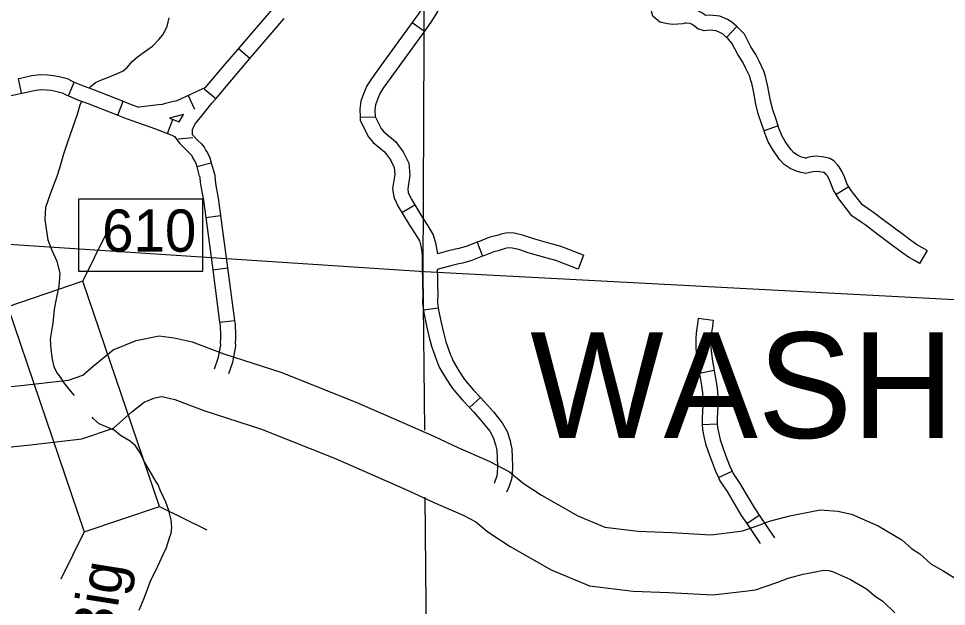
# Model space of a CAD drawing. Extents: x -492261 to -432772, y 1441225 to 1452922.
# Drawn here: x -463909.6 to -463644.7, y 1451410.6 to 1451578.4 of the extents above; entities that cross this region are included whole.
import ezdxf

# ---------------------------------------------------------------- set-up
doc = ezdxf.new("R2010")
doc.units = 0
doc.layers.add('Default', color=7, linetype='Continuous')

msp = doc.modelspace()

# ---------------------------------------------------------------- linework, layer by layer
at = {"layer": 'Default'}
for p, q in [((-463797.21, 1451577.35), (-463793.73, 1451574.84)), ((-463704.55, 1451576.19), (-463707.46, 1451573.04)), ((-463843.55, 1451567.04), (-463846.8, 1451569.83)), ((-463908.78, 1451557.09), (-463909.59, 1451561.3)), ((-463895.36, 1451556.36), (-463893.73, 1451560.32)), ((-463853.3, 1451555.56), (-463856.58, 1451558.32)), ((-463881.28, 1451550.86), (-463879.71, 1451554.85)), ((-463861.14, 1451556.48), (-463859.35, 1451552.58)), ((-463867.1, 1451545.64), (-463865.57, 1451549.65)), ((-463812.07, 1451550.25), (-463807.79, 1451550.39)), ((-463692.69, 1451547.78), (-463696.75, 1451546.41)), ((-463859.79, 1451544.41), (-463864.06, 1451544.04)), ((-463858.73, 1451536.18), (-463854.57, 1451537.23)), ((-463672.49, 1451530.41), (-463676.17, 1451528.21)), ((-463800.13, 1451523.01), (-463796.47, 1451525.24)), ((-463856.14, 1451521.61), (-463851.89, 1451522.17)), ((-463891.21, 1451503.41), (-463884.54, 1451516.94)), ((-463778.61, 1451514.56), (-463777.11, 1451510.54)), ((-463650.2, 1451512.21), (-463652.31, 1451508.49)), ((-463748.3, 1451510.9), (-463749.85, 1451506.9)), ((-463854.16, 1451506.65), (-463849.91, 1451507.22)), ((-463794, 1451495.26), (-463789.75, 1451495.81)), ((-463852.18, 1451491.7), (-463847.93, 1451492.26)), ((-463715.51, 1451492.87), (-463711.26, 1451492.31)), ((-463715.19, 1451477.22), (-463710.98, 1451478.03)), ((-463780.87, 1451467.33), (-463777.71, 1451470.23)), ((-463714.36, 1451462.51), (-463710.08, 1451462.74)), ((-463709.77, 1451447.39), (-463705.87, 1451449.17)), ((-463869.38, 1451439.13), (-463855.85, 1451432.46)), ((-463701.68, 1451434.26), (-463698.13, 1451436.66)), ((-463890.81, 1451431.86), (-463897.48, 1451418.32))]:
    msp.add_line(p, q, dxfattribs=at)
for points in [[(-463790.72, 1451742.44), (-463793.52, 1451659.39), (-463794.14, 1451505.86), (-463793.73, 1451460.92)], [(-463789.44, 1451589.89), (-463790.22, 1451588.38), (-463792.32, 1451584.92), (-463794.15, 1451581.78), (-463795.44, 1451579.79), (-463797.21, 1451577.35)], [(-463785.63, 1451587.93), (-463786.48, 1451586.29), (-463788.64, 1451582.73), (-463790.5, 1451579.53), (-463791.91, 1451577.37), (-463793.73, 1451574.84)], [(-463719.23, 1451577.08), (-463719.95, 1451576.89), (-463722.77, 1451576.76), (-463724.27, 1451576.97), (-463726.5, 1451577.41), (-463728.51, 1451579.11), (-463728.88, 1451580.55), (-463728.96, 1451582.01), (-463728.99, 1451585.28), (-463729.26, 1451586.93), (-463729.4, 1451587.74)], [(-463846.8, 1451569.83), (-463836.99, 1451581.24), (-463836.93, 1451581.31)], [(-463704.55, 1451576.19), (-463705.9, 1451577.44), (-463707.22, 1451578.18), (-463709.32, 1451579.11), (-463712.3, 1451579.38), (-463713.35, 1451579.29), (-463713.56, 1451579.36), (-463714.27, 1451579.94), (-463715.22, 1451580.46), (-463716.55, 1451581.18), (-463719.28, 1451581.5), (-463720.3, 1451581.23)], [(-463889.24, 1451558.7), (-463889.12, 1451558.9), (-463887.65, 1451560.18), (-463885.89, 1451560.94), (-463883.61, 1451561.83), (-463882.53, 1451562.24), (-463881.34, 1451562.71), (-463879.75, 1451563.47), (-463878.45, 1451564.57), (-463877.16, 1451566.19), (-463875.63, 1451567.52), (-463873.25, 1451569.21), (-463871.33, 1451570.6), (-463869.52, 1451572.46), (-463868.4, 1451573.78), (-463867.17, 1451576.14), (-463866.56, 1451578.61)], [(-463843.55, 1451567.04), (-463833.77, 1451578.41), (-463833.74, 1451578.44)], [(-463797.21, 1451577.35), (-463806.04, 1451565.12)], [(-463707.46, 1451573.04), (-463708.44, 1451573.95), (-463709.14, 1451574.34), (-463710.41, 1451574.91), (-463712.31, 1451575.08), (-463713.85, 1451574.95), (-463715.65, 1451575.53), (-463716.68, 1451576.37), (-463717.27, 1451576.7), (-463717.86, 1451577.02), (-463718.97, 1451577.15), (-463719.23, 1451577.08)], [(-463696.46, 1451562.29), (-463696.8, 1451563.43), (-463698.06, 1451566.07), (-463699.09, 1451568.15), (-463700.51, 1451570.35), (-463702.36, 1451573.96), (-463704.02, 1451575.71), (-463704.55, 1451576.19)], [(-463793.73, 1451574.84), (-463802.57, 1451562.61)], [(-463700.57, 1451561.06), (-463700.82, 1451561.89), (-463701.91, 1451564.2), (-463702.82, 1451566.03), (-463704.23, 1451568.21), (-463705.89, 1451571.45), (-463707.03, 1451572.65), (-463707.46, 1451573.04)], [(-463856.24, 1451558.72), (-463850.48, 1451565.55), (-463846.8, 1451569.83)], [(-463853.3, 1451555.56), (-463847.22, 1451562.78), (-463843.55, 1451567.04)], [(-463806.04, 1451565.12), (-463808.83, 1451561.27), (-463810.15, 1451559.2), (-463811.07, 1451556.93), (-463811.83, 1451554.89), (-463812.15, 1451552.53), (-463812.07, 1451550.25)], [(-463909.59, 1451561.3), (-463909.01, 1451561.41), (-463905.9, 1451562.14), (-463903.46, 1451562.5), (-463901.3, 1451562.33), (-463899.64, 1451562.22), (-463897.65, 1451561.75), (-463895.67, 1451561.31), (-463894.13, 1451560.49), (-463893.73, 1451560.32)], [(-463802.57, 1451562.61), (-463805.28, 1451558.86), (-463806.32, 1451557.23), (-463807.07, 1451555.37), (-463807.64, 1451553.84), (-463807.85, 1451552.31), (-463807.79, 1451550.39)], [(-463692.69, 1451547.78), (-463693.3, 1451549.59), (-463694.26, 1451552.42), (-463694.87, 1451554.9), (-463695.36, 1451557.52), (-463695.67, 1451559.08), (-463696.09, 1451561.04), (-463696.46, 1451562.29)], [(-463893.73, 1451560.32), (-463890.89, 1451559.16), (-463888.45, 1451558.28), (-463879.71, 1451554.85)], [(-463696.75, 1451546.41), (-463697.36, 1451548.22), (-463698.38, 1451551.22), (-463699.06, 1451553.99), (-463699.57, 1451556.71), (-463699.87, 1451558.22), (-463700.25, 1451559.98), (-463700.57, 1451561.06)], [(-463924.18, 1451554.85), (-463923.61, 1451554.82), (-463921.44, 1451554.91), (-463919.68, 1451555.11), (-463918.21, 1451555.24), (-463916.09, 1451555.57), (-463910.36, 1451556.78), (-463908.78, 1451557.09)], [(-463908.78, 1451557.09), (-463908.12, 1451557.21), (-463905.09, 1451557.93), (-463903.31, 1451558.19), (-463901.6, 1451558.06), (-463900.29, 1451557.97), (-463898.62, 1451557.57), (-463897.17, 1451557.25), (-463895.95, 1451556.61), (-463895.36, 1451556.36)], [(-463856.24, 1451558.72), (-463864.44, 1451554.97), (-463866.47, 1451554.43), (-463867.6, 1451554.14), (-463868.61, 1451553.93), (-463869.59, 1451553.81), (-463875.26, 1451553.18)], [(-463893.59, 1451470.8), (-463895.12, 1451472.62), (-463896.62, 1451474.49), (-463897.55, 1451475.97), (-463898.65, 1451477.38), (-463899.4, 1451479.03), (-463899.88, 1451481.09), (-463900.26, 1451484), (-463900.46, 1451486.92), (-463899.71, 1451491.5), (-463899.35, 1451495.4), (-463898.91, 1451497.46), (-463897.99, 1451502.05), (-463897.74, 1451505.77), (-463898.52, 1451509.08), (-463899.98, 1451512.21), (-463901.09, 1451515.17), (-463902.01, 1451521.05), (-463901.76, 1451524.6), (-463900.38, 1451528.68), (-463898.55, 1451533.39), (-463897.77, 1451535.81), (-463896.62, 1451539.82), (-463895.51, 1451543.27), (-463894.13, 1451547.35), (-463892.8, 1451551.14), (-463891.97, 1451553.84), (-463891.59, 1451554.7)], [(-463895.36, 1451556.36), (-463892.44, 1451555.16), (-463889.96, 1451554.26), (-463881.28, 1451550.86)], [(-463879.71, 1451554.85), (-463877.4, 1451553.94), (-463875.26, 1451553.18)], [(-463859.97, 1451545.27), (-463859.89, 1451546.75), (-463859.72, 1451547.28), (-463859.03, 1451548.44), (-463857.25, 1451550.64), (-463854.4, 1451554.26), (-463853.3, 1451555.56)], [(-463881.28, 1451550.86), (-463878.9, 1451549.93), (-463870.47, 1451546.93), (-463867.1, 1451545.64)], [(-463862.45, 1451551.07), (-463866.47, 1451549.99)], [(-463866.47, 1451549.99), (-463863.72, 1451548.94)], [(-463863.72, 1451548.94), (-463862.45, 1451551.07)], [(-463812.07, 1451550.25), (-463812.04, 1451549.43), (-463809.74, 1451544.73), (-463808.35, 1451543), (-463805.08, 1451540.35), (-463803.41, 1451538.09), (-463803.07, 1451537.41)], [(-463807.79, 1451550.49), (-463806.1, 1451547.04), (-463805.3, 1451546.05), (-463801.95, 1451543.33), (-463799.76, 1451540.35), (-463799.26, 1451539.38)], [(-463685.62, 1451534.38), (-463686.25, 1451534.52), (-463687.51, 1451534.85), (-463689.26, 1451535.65), (-463691.02, 1451536.77), (-463692.37, 1451538.22), (-463694.36, 1451541.1), (-463695.56, 1451543.22), (-463696.51, 1451545.7), (-463696.75, 1451546.41)], [(-463684.68, 1451538.56), (-463685.23, 1451538.68), (-463686.07, 1451538.9), (-463687.21, 1451539.42), (-463688.25, 1451540.09), (-463689.02, 1451540.92), (-463690.72, 1451543.37), (-463691.67, 1451545.05), (-463692.48, 1451547.16), (-463692.69, 1451547.78)], [(-463867.1, 1451545.64), (-463865.85, 1451545.16), (-463865.08, 1451544.72), (-463863.54, 1451542.8), (-463861.43, 1451540.62), (-463860.51, 1451539.71), (-463860.23, 1451539.38), (-463859.86, 1451538.6), (-463859.32, 1451537.84), (-463858.98, 1451537.17), (-463858.73, 1451536.18)], [(-463859.97, 1451545.27), (-463858.39, 1451543.64), (-463857.35, 1451542.62), (-463856.59, 1451541.71), (-463856.15, 1451540.78), (-463855.64, 1451540.06), (-463854.94, 1451538.69), (-463854.57, 1451537.23)], [(-463799.26, 1451539.38), (-463798.13, 1451537.19), (-463797.89, 1451533.71), (-463798.46, 1451529.85), (-463798.31, 1451528.66), (-463797.34, 1451526.68), (-463796.47, 1451525.24)], [(-463672.49, 1451530.41), (-463673.07, 1451531.37), (-463673.8, 1451533.23), (-463674.41, 1451534.68), (-463675.27, 1451536.13), (-463675.75, 1451536.67), (-463676.78, 1451537.8), (-463677.91, 1451538.51), (-463679.1, 1451538.72), (-463680.25, 1451538.91), (-463681.84, 1451539.13), (-463683.57, 1451538.93), (-463684.93, 1451538.61), (-463684.68, 1451538.56)], [(-463858.73, 1451536.18), (-463858.61, 1451535.73), (-463857.98, 1451533.44), (-463857.94, 1451533.4), (-463857.83, 1451532.95), (-463857.71, 1451531.67), (-463857.45, 1451530.03), (-463856.79, 1451526.52), (-463856.14, 1451521.61)], [(-463854.57, 1451537.23), (-463854.47, 1451536.82), (-463854.16, 1451535.69), (-463854.08, 1451535.61), (-463853.59, 1451533.67), (-463853.46, 1451532.2), (-463853.23, 1451530.76), (-463852.56, 1451527.19), (-463851.89, 1451522.17)], [(-463803.07, 1451537.41), (-463802.34, 1451536.01), (-463802.2, 1451533.88), (-463802.79, 1451529.89), (-463802.47, 1451527.42), (-463801.11, 1451524.62), (-463800.13, 1451523.01)], [(-463676.17, 1451528.21), (-463676.93, 1451529.48), (-463677.77, 1451531.62), (-463678.24, 1451532.75), (-463678.74, 1451533.59), (-463678.94, 1451533.8), (-463679.52, 1451534.44), (-463679.83, 1451534.5), (-463680.89, 1451534.67), (-463681.89, 1451534.81), (-463682.83, 1451534.7), (-463684.91, 1451534.22), (-463685.62, 1451534.38)], [(-463662.33, 1451520.69), (-463665.45, 1451523.02), (-463666.34, 1451523.6), (-463668.65, 1451525.24), (-463669.77, 1451526.7), (-463671.87, 1451529.36), (-463672.49, 1451530.41)], [(-463664.89, 1451517.26), (-463667.91, 1451519.51), (-463668.75, 1451520.06), (-463671.65, 1451522.11), (-463673.15, 1451524.07), (-463675.41, 1451526.92), (-463676.17, 1451528.21)], [(-463892.5, 1451506.32), (-463856.93, 1451506.32), (-463856.93, 1451526.87), (-463892.5, 1451526.87), (-463892.5, 1451506.32)], [(-463796.47, 1451525.24), (-463794.34, 1451521.74), (-463792.7, 1451519.22), (-463791.22, 1451516.7), (-463790.51, 1451514.44), (-463789.98, 1451511.22)], [(-463851.89, 1451522.17), (-463849.91, 1451507.22)], [(-463800.13, 1451523.01), (-463797.96, 1451519.46), (-463796.35, 1451516.97), (-463795.16, 1451514.95), (-463794.69, 1451513.44), (-463794.44, 1451511.91), (-463794.39, 1451510.53)], [(-463556.78, 1451493.58), (-463640.44, 1451498.04), (-463793.68, 1451506.14), (-463942.87, 1451515.91), (-464056.58, 1451522.01)], [(-463856.14, 1451521.61), (-463854.16, 1451506.65)], [(-463650.2, 1451512.21), (-463651.69, 1451513.06), (-463653.2, 1451513.91), (-463654.57, 1451514.86), (-463657.34, 1451516.97), (-463662.33, 1451520.69)], [(-463762.72, 1451515.66), (-463765.67, 1451516.61), (-463768.1, 1451517.13), (-463770.12, 1451517.23), (-463771.79, 1451516.9), (-463772.54, 1451516.62), (-463773.82, 1451516.26), (-463775.27, 1451515.88), (-463777.8, 1451514.86), (-463778.61, 1451514.56)], [(-463652.31, 1451508.49), (-463653.8, 1451509.33), (-463655.48, 1451510.27), (-463657.09, 1451511.4), (-463659.92, 1451513.55), (-463664.89, 1451517.26)], [(-463778.61, 1451514.56), (-463781.75, 1451513.38), (-463783.92, 1451512.77), (-463784.86, 1451512.54), (-463787.2, 1451512.03), (-463789.98, 1451511.22)], [(-463748.3, 1451510.9), (-463754.91, 1451513.47), (-463757.54, 1451514.14), (-463762.14, 1451515.47), (-463762.72, 1451515.66)], [(-463764.04, 1451511.58), (-463766.77, 1451512.46), (-463768.66, 1451512.87), (-463769.8, 1451512.92), (-463770.62, 1451512.76), (-463771.21, 1451512.54), (-463772.69, 1451512.12), (-463773.92, 1451511.8), (-463776.25, 1451510.86), (-463777.11, 1451510.54)], [(-463749.85, 1451506.9), (-463756.22, 1451509.38), (-463758.67, 1451510.01), (-463763.39, 1451511.37), (-463764.04, 1451511.58)], [(-463794.39, 1451510.53), (-463794.36, 1451509.38), (-463794.33, 1451506.81), (-463794.24, 1451504.23), (-463794.22, 1451502.2), (-463794.2, 1451499.99), (-463794.23, 1451497.06), (-463794, 1451495.26)], [(-463777.11, 1451510.54), (-463780.42, 1451509.3), (-463782.83, 1451508.63), (-463783.89, 1451508.36), (-463786.14, 1451507.87), (-463790.04, 1451506.74)], [(-463854.16, 1451506.65), (-463852.18, 1451491.7)], [(-463849.91, 1451507.22), (-463847.93, 1451492.26)], [(-463790.04, 1451506.74), (-463789.96, 1451504.33), (-463789.94, 1451502.24), (-463789.91, 1451499.99), (-463789.94, 1451497.31), (-463789.75, 1451495.81)], [(-463789.75, 1451495.81), (-463789.66, 1451495.14), (-463788.96, 1451491.65), (-463788.26, 1451488.75), (-463787.57, 1451486.11), (-463786.27, 1451482.43), (-463786.01, 1451481.8)], [(-463794, 1451495.26), (-463793.89, 1451494.44), (-463793.15, 1451490.73), (-463792.42, 1451487.7), (-463791.68, 1451484.86), (-463790.28, 1451480.9), (-463789.98, 1451480.17)], [(-463852.18, 1451491.7), (-463852.04, 1451490.67), (-463851.91, 1451488.1), (-463851.95, 1451486.96), (-463852.01, 1451485.99), (-463851.95, 1451485.16), (-463852.68, 1451481.34), (-463853.7, 1451478.35)], [(-463847.93, 1451492.26), (-463847.77, 1451491.06), (-463847.62, 1451488.14), (-463847.67, 1451486.77), (-463847.71, 1451486.02), (-463847.63, 1451484.9), (-463848.53, 1451480.24), (-463849.64, 1451476.98)], [(-463715.51, 1451492.87), (-463715.62, 1451492.04), (-463715.72, 1451491.1), (-463715.99, 1451489.43), (-463716.21, 1451487.35), (-463716.26, 1451485.73), (-463716.24, 1451484.34), (-463716.04, 1451482.32), (-463715.72, 1451479.94), (-463715.19, 1451477.22)], [(-463711.26, 1451492.31), (-463711.37, 1451491.53), (-463711.47, 1451490.53), (-463711.74, 1451488.86), (-463711.93, 1451487.06), (-463711.97, 1451485.69), (-463711.96, 1451484.57), (-463711.78, 1451482.82), (-463711.49, 1451480.63), (-463710.98, 1451478.03)], [(-463925.34, 1451471.98), (-463908.9, 1451473.62), (-463895.32, 1451475.22), (-463891.22, 1451476.61), (-463888.27, 1451479.2), (-463882.58, 1451483.83), (-463876, 1451486.48), (-463869.47, 1451487.86), (-463865.13, 1451487.26), (-463860.06, 1451486.13), (-463851.02, 1451482.67), (-463834.41, 1451477.33), (-463812.8, 1451468.7), (-463801, 1451463.6), (-463791.03, 1451459.15), (-463784.17, 1451455.96), (-463775.22, 1451452.09), (-463769.41, 1451449), (-463765.47, 1451445.73), (-463760.26, 1451442.35), (-463749.95, 1451436.39), (-463742.17, 1451433.21), (-463732.7, 1451432.02), (-463723.14, 1451431.63), (-463711.96, 1451431.03), (-463704.19, 1451431.98), (-463702.92, 1451432.11), (-463698.71, 1451433.56), (-463695.2, 1451434.95), (-463689.36, 1451436.45), (-463680.68, 1451438.15), (-463675.7, 1451437.79), (-463671.74, 1451436.89), (-463664.2, 1451433.55), (-463657.43, 1451429.58), (-463654.62, 1451427.12), (-463652.28, 1451425.61), (-463649.15, 1451422.69), (-463645.45, 1451420.59), (-463636.76, 1451415.25)], [(-463789.98, 1451480.17), (-463789.38, 1451478.72), (-463787.53, 1451475.58), (-463785.69, 1451472.81), (-463782.87, 1451469.51), (-463780.87, 1451467.33)], [(-463786.01, 1451481.8), (-463785.53, 1451480.63), (-463783.9, 1451477.86), (-463782.26, 1451475.4), (-463779.66, 1451472.36), (-463777.71, 1451470.23)], [(-463715.19, 1451477.22), (-463715.17, 1451477.11), (-463714.57, 1451473.53), (-463714.34, 1451471.52), (-463714.15, 1451468.63), (-463714.28, 1451466.59), (-463714.44, 1451464), (-463714.36, 1451462.51)], [(-463710.98, 1451478.03), (-463710.95, 1451477.87), (-463710.33, 1451474.13), (-463710.07, 1451471.91), (-463709.85, 1451468.63), (-463710.01, 1451466.32), (-463710.15, 1451463.99), (-463710.08, 1451462.74)], [(-463923.72, 1451454.92), (-463907.05, 1451456.58), (-463891.52, 1451458.41), (-463882.49, 1451461.47), (-463877.21, 1451466.1), (-463873.77, 1451468.9), (-463870.99, 1451470.02), (-463868.84, 1451470.47), (-463868.16, 1451470.38), (-463865.01, 1451469.67), (-463856.71, 1451466.5), (-463840.22, 1451461.19), (-463819.38, 1451452.87), (-463807.9, 1451447.9), (-463798.13, 1451443.54), (-463791.18, 1451440.32), (-463782.67, 1451436.63), (-463779.01, 1451434.69), (-463775.65, 1451431.9), (-463769.22, 1451427.72), (-463757.51, 1451420.97), (-463746.57, 1451416.48), (-463734.12, 1451414.92), (-463723.94, 1451414.51), (-463711.38, 1451413.84), (-463702.26, 1451414.95), (-463699.18, 1451415.27), (-463692.78, 1451417.48), (-463689.89, 1451418.61), (-463685.57, 1451419.73), (-463679.64, 1451420.89), (-463678.23, 1451420.79), (-463677.17, 1451420.55), (-463672.04, 1451418.27), (-463667.51, 1451415.61), (-463664.96, 1451413.38), (-463662.85, 1451412.03), (-463659.36, 1451408.77)], [(-463777.71, 1451470.23), (-463776.56, 1451468.98), (-463774.03, 1451466.15), (-463771.52, 1451463.02), (-463770.1, 1451460.52), (-463769.24, 1451457.81), (-463769.02, 1451456.83)], [(-463780.87, 1451467.33), (-463779.73, 1451466.1), (-463777.3, 1451463.38), (-463775.07, 1451460.61), (-463774.05, 1451458.79), (-463773.38, 1451456.71), (-463773.21, 1451455.93)], [(-463875.18, 1451409.45), (-463873.74, 1451412.9), (-463872.79, 1451415.49), (-463871.79, 1451418.07), (-463870.45, 1451420.66), (-463869.28, 1451423.31), (-463868.33, 1451425.38), (-463867.38, 1451427.39), (-463866.55, 1451429.86), (-463866.06, 1451431.53), (-463865.79, 1451433.13), (-463866.04, 1451435.3), (-463866.7, 1451437.93), (-463867.52, 1451440.32), (-463868.28, 1451441.97), (-463869.04, 1451443.62), (-463869.74, 1451445.27), (-463870.32, 1451446.18), (-463873.63, 1451451.87), (-463875.08, 1451454.71), (-463876.24, 1451456.41), (-463877.74, 1451457.77), (-463880.49, 1451459.4), (-463882.33, 1451460.92), (-463886.57, 1451462.7), (-463888.3, 1451464.23), (-463888.62, 1451464.6)], [(-463714.36, 1451462.51), (-463714.28, 1451461.1), (-463713.89, 1451459.1), (-463713.44, 1451457.02), (-463712.68, 1451454.83), (-463711.73, 1451452.24), (-463710.59, 1451449.2), (-463709.77, 1451447.39)], [(-463710.08, 1451462.74), (-463710.02, 1451461.63), (-463709.69, 1451459.97), (-463709.3, 1451458.17), (-463708.64, 1451456.26), (-463707.72, 1451453.73), (-463706.63, 1451450.84), (-463705.87, 1451449.17)], [(-463773.21, 1451455.93), (-463773.02, 1451455.05), (-463772.95, 1451453.02), (-463772.87, 1451450.58), (-463772.96, 1451448.56), (-463773.03, 1451447.9), (-463773.81, 1451445.68)], [(-463769.02, 1451456.83), (-463768.75, 1451455.59), (-463768.67, 1451453.16), (-463768.58, 1451450.56), (-463768.68, 1451448.24), (-463768.82, 1451446.95), (-463769.53, 1451444.93), (-463770.25, 1451443.19)], [(-463705.87, 1451449.17), (-463705.56, 1451448.5), (-463703.67, 1451445.66), (-463701.54, 1451442.19), (-463699.59, 1451438.82), (-463698.13, 1451436.66)], [(-463709.77, 1451447.39), (-463709.32, 1451446.41), (-463707.28, 1451443.35), (-463705.23, 1451440), (-463703.23, 1451436.55), (-463701.68, 1451434.26)], [(-463793.56, 1451441.78), (-463792.82, 1451359.99)], [(-463698.13, 1451436.66), (-463693.73, 1451430.16)], [(-463701.68, 1451434.26), (-463697.83, 1451428.58)]]:
    msp.add_lwpolyline(points, dxfattribs=at)
for points in [[(-463892.5, 1451506.32), (-463856.93, 1451506.32), (-463856.93, 1451526.87), (-463892.5, 1451526.87)], [(-463869.38, 1451439.13), (-463891.21, 1451503.41), (-463912.64, 1451496.14), (-463890.81, 1451431.86)]]:
    msp.add_lwpolyline(points, close=True, dxfattribs=at)

# ---------------------------------------------------------------- texts
for s, height, p in [('610', 12.057, (-463885.73, 1451511.86)), ('WASHITA', 30.171, (-463763.5, 1451458.66))]:
    msp.add_text(s, height=height, dxfattribs=at).set_placement(p)
msp.add_text('Big', height=12.069, rotation=81, dxfattribs=at).set_placement((-463882.96, 1451399.38))

doc.saveas('drawing.dxf')
